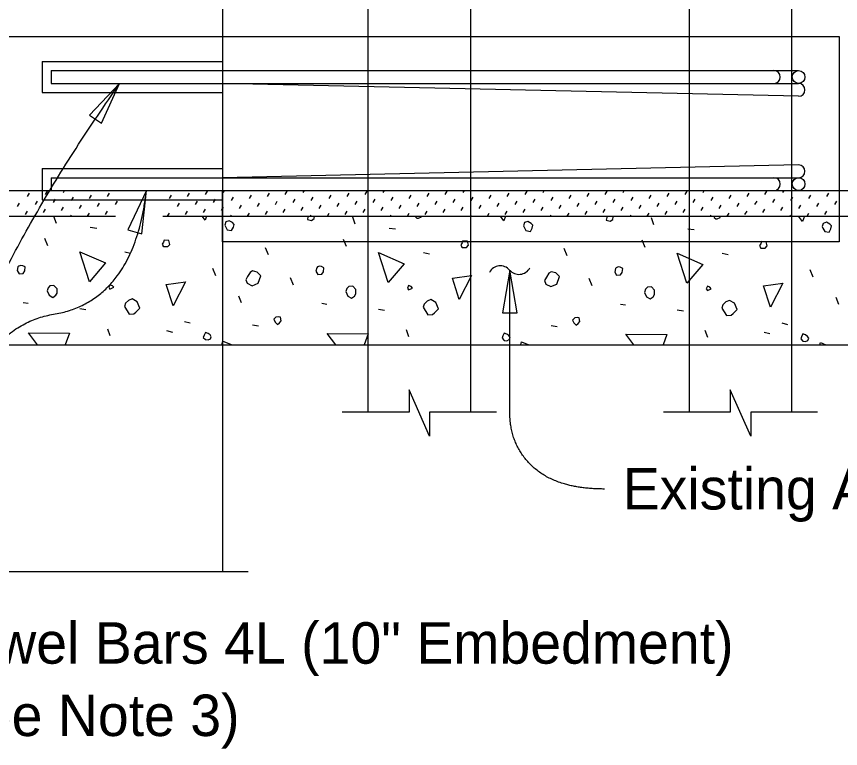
# Model space of a CAD drawing. Extents: x 1 to 39.2, y 0 to 26.
# Drawn here: x 29.063 to 33.072, y 8.169 to 11.73 of the extents above; entities that cross this region are included whole.
import ezdxf

# ---------------------------------------------------------------- set-up
doc = ezdxf.new("R2010")
doc.units = 0
for name, color, linetype in [('Dimension', 7, 'Continuous'), ('Miscellaneous', 7, 'Continuous'), ('Rebar', 7, 'Continuous'), ('TextStructures', 7, 'Continuous'), ('TrafBarrierConc', 7, 'Continuous')]:
    doc.layers.add(name, color=color, linetype=linetype)

msp = doc.modelspace()

# ---------------------------------------------------------------- linework, layer by layer
at = {"layer": 'Dimension'}
for points in [[(29.5637, 11.4029), (29.4175, 11.2504), (29.4758, 11.2108)], [(29.695, 10.8824), (29.6045, 10.6915), (29.6724, 10.6724)], [(31.4629, 10.4959), (31.4278, 10.2877), (31.4984, 10.2877)]]:
    msp.add_lwpolyline(points, close=True, dxfattribs=at)
for points in [[(31.3975, 9.8041), (31.0722, 9.8041), (31.0722, 9.6878), (30.9728, 9.9128), (30.9728, 9.8041), (30.6475, 9.8041)], [(32.96, 9.8041), (32.6347, 9.8041), (32.6347, 9.6878), (32.5353, 9.9128), (32.5353, 9.8041), (32.21, 9.8041)], [(30.1906, 9.0282), (28.3006, 9.0282), (28.3006, 8.912), (28.2013, 9.137), (28.2013, 9.0282), (26.9206, 9.0282)]]:
    msp.add_lwpolyline(points, dxfattribs=at)
for centre, start, end in [((31.4168, 10.4571), 40.6168, 152.344), ((31.5073, 10.5347), 220.6168, 332.344)]:
    msp.add_arc(centre, 0.0596, start, end, dxfattribs=at)
for points in [[(28.5243, 8.6625), (28.4652, 8.6625), (28.4062, 8.6794), (28.4062, 8.9032), (28.932, 10.5005), (29.5637, 11.4029)], [(28.5774, 9.3946), (28.84, 10.2158), (29.6329, 10.3433), (29.6949, 10.8824)], [(31.9229, 9.431), (31.6965, 9.431), (31.4629, 9.6392), (31.4629, 9.9681), (31.4629, 10.4959)]]:
    msp.add_open_spline(points, degree=2, dxfattribs=at)
at = {"layer": 'Miscellaneous'}
for p, q in [((29.1166, 10.8538), (29.1263, 10.8706)), ((29.2041, 10.8635), (29.2138, 10.8803)), ((29.2916, 10.8732), (29.2972, 10.883)), ((29.5055, 10.8538), (29.5152, 10.8706)), ((29.8944, 10.8538), (29.9041, 10.8706)), ((29.9819, 10.8635), (29.9916, 10.8803)), ((30.0694, 10.8732), (30.075, 10.883)), ((30.2833, 10.8538), (30.293, 10.8706)), ((30.3708, 10.8635), (30.3805, 10.8803)), ((30.4583, 10.8732), (30.4639, 10.883)), ((30.6722, 10.8538), (30.6819, 10.8706)), ((30.7597, 10.8635), (30.7694, 10.8803)), ((30.8472, 10.8732), (30.8528, 10.883)), ((31.0611, 10.8538), (31.0708, 10.8706)), ((31.1486, 10.8635), (31.1583, 10.8803)), ((31.2361, 10.8732), (31.2418, 10.883)), ((31.45, 10.8538), (31.4597, 10.8706)), ((31.5375, 10.8635), (31.5473, 10.8803)), ((31.625, 10.8732), (31.6307, 10.883)), ((31.8389, 10.8538), (31.8487, 10.8706)), ((31.9264, 10.8635), (31.9362, 10.8803)), ((32.0139, 10.8732), (32.0196, 10.883)), ((32.2278, 10.8538), (32.2376, 10.8706)), ((32.3153, 10.8635), (32.3251, 10.8803)), ((32.4029, 10.8732), (32.4085, 10.883)), ((32.6168, 10.8538), (32.6265, 10.8706)), ((32.7043, 10.8635), (32.714, 10.8803)), ((32.7918, 10.8732), (32.7974, 10.883)), ((33.0057, 10.8538), (33.0154, 10.8706)), ((29.1555, 10.8149), (29.1652, 10.8317)), ((29.243, 10.8246), (29.2527, 10.8414)), ((29.3305, 10.8344), (29.3402, 10.8511)), ((29.418, 10.8441), (29.4277, 10.8609)), ((29.5444, 10.8149), (29.5541, 10.8317)), ((29.8069, 10.8441), (29.8166, 10.8609)), ((29.9333, 10.8149), (29.943, 10.8317)), ((30.0208, 10.8246), (30.0305, 10.8414)), ((30.1083, 10.8344), (30.118, 10.8511)), ((30.1958, 10.8441), (30.2055, 10.8609)), ((30.3222, 10.8149), (30.3319, 10.8317)), ((30.4097, 10.8246), (30.4194, 10.8414)), ((30.4972, 10.8344), (30.5069, 10.8511)), ((30.5847, 10.8441), (30.5944, 10.8609)), ((30.7111, 10.8149), (30.7208, 10.8317)), ((30.7986, 10.8246), (30.8083, 10.8414)), ((30.8861, 10.8344), (30.8958, 10.8511)), ((30.9736, 10.8441), (30.9833, 10.8609)), ((31.1, 10.8149), (31.1097, 10.8317)), ((31.1875, 10.8246), (31.1972, 10.8414)), ((31.275, 10.8344), (31.2847, 10.8511)), ((31.3625, 10.8441), (31.3722, 10.8609)), ((31.4889, 10.8149), (31.4986, 10.8317)), ((31.5764, 10.8246), (31.5861, 10.8414)), ((31.6639, 10.8344), (31.6736, 10.8511)), ((31.7514, 10.8441), (31.7612, 10.8609)), ((31.8778, 10.8149), (31.8875, 10.8317)), ((31.9653, 10.8246), (31.9751, 10.8414)), ((32.0528, 10.8344), (32.0626, 10.8511)), ((32.1403, 10.8441), (32.1501, 10.8609)), ((32.2667, 10.8149), (32.2765, 10.8317)), ((32.3542, 10.8246), (32.364, 10.8414)), ((32.4417, 10.8344), (32.4515, 10.8511)), ((32.5292, 10.8441), (32.539, 10.8609)), ((32.6556, 10.8149), (32.6654, 10.8317)), ((32.7431, 10.8246), (32.7529, 10.8414)), ((32.8307, 10.8344), (32.8404, 10.8511)), ((32.9182, 10.8441), (32.9279, 10.8609)), ((33.0446, 10.8149), (33.0543, 10.8317)), ((29.068, 10.8052), (29.0777, 10.822)), ((29.1944, 10.776), (29.2041, 10.7928)), ((29.2819, 10.7857), (29.2916, 10.8025)), ((29.3694, 10.7955), (29.3791, 10.8123)), ((29.4569, 10.8052), (29.4666, 10.822)), ((29.8458, 10.8052), (29.8555, 10.822)), ((29.9722, 10.776), (29.9819, 10.7928)), ((30.0597, 10.7857), (30.0694, 10.8025)), ((30.1472, 10.7955), (30.1569, 10.8123)), ((30.2347, 10.8052), (30.2444, 10.822)), ((30.3611, 10.776), (30.3708, 10.7928)), ((30.4486, 10.7857), (30.4583, 10.8025)), ((30.5361, 10.7955), (30.5458, 10.8123)), ((30.6236, 10.8052), (30.6333, 10.822)), ((30.75, 10.776), (30.7597, 10.7928)), ((30.8375, 10.7857), (30.8472, 10.8025)), ((30.925, 10.7955), (30.9347, 10.8123)), ((31.0125, 10.8052), (31.0222, 10.822)), ((31.1389, 10.776), (31.1486, 10.7928)), ((31.2264, 10.7857), (31.2361, 10.8025)), ((31.3139, 10.7955), (31.3236, 10.8123)), ((31.4014, 10.8052), (31.4111, 10.822)), ((31.5278, 10.776), (31.5375, 10.7928)), ((31.6153, 10.7857), (31.625, 10.8025)), ((31.7028, 10.7955), (31.7125, 10.8123)), ((31.7903, 10.8052), (31.8, 10.822)), ((31.9167, 10.776), (31.9264, 10.7928)), ((32.0042, 10.7857), (32.0139, 10.8025)), ((32.0917, 10.7955), (32.1014, 10.8123)), ((32.1792, 10.8052), (32.189, 10.822)), ((32.3056, 10.776), (32.3153, 10.7928)), ((32.3931, 10.7857), (32.4029, 10.8025)), ((32.4806, 10.7955), (32.4904, 10.8123)), ((32.5681, 10.8052), (32.5779, 10.822)), ((32.6945, 10.776), (32.7043, 10.7928)), ((32.782, 10.7857), (32.7918, 10.8025)), ((32.8695, 10.7955), (32.8793, 10.8123)), ((32.957, 10.8052), (32.9668, 10.822)), ((29.1069, 10.7663), (29.1166, 10.7831)), ((29.2577, 10.7234), (29.2453, 10.757)), ((29.3272, 10.758), (29.3305, 10.7636)), ((29.4091, 10.758), (29.418, 10.7734)), ((29.4958, 10.7663), (29.5055, 10.7831)), ((29.798, 10.758), (29.8069, 10.7734)), ((29.8847, 10.7663), (29.8944, 10.7831)), ((30.105, 10.758), (30.1083, 10.7636)), ((30.1869, 10.758), (30.1958, 10.7734)), ((30.2736, 10.7663), (30.2833, 10.7831)), ((30.4939, 10.758), (30.4972, 10.7636)), ((30.5758, 10.758), (30.5847, 10.7734)), ((30.6625, 10.7663), (30.6722, 10.7831)), ((30.7108, 10.7199), (30.6984, 10.7535)), ((30.8828, 10.758), (30.8861, 10.7636)), ((30.9647, 10.758), (30.9736, 10.7734)), ((31.0514, 10.7663), (31.0611, 10.7831)), ((31.2717, 10.758), (31.275, 10.7636)), ((31.3536, 10.758), (31.3625, 10.7734)), ((31.4403, 10.7663), (31.45, 10.7831)), ((31.6606, 10.758), (31.6639, 10.7636)), ((31.7425, 10.758), (31.7514, 10.7734)), ((31.8292, 10.7663), (31.8389, 10.7831)), ((32.0496, 10.758), (32.0528, 10.7636)), ((32.1314, 10.758), (32.1403, 10.7734)), ((32.1639, 10.7163), (32.1515, 10.7499)), ((32.2181, 10.7663), (32.2278, 10.7831)), ((32.4385, 10.758), (32.4417, 10.7636)), ((32.5203, 10.758), (32.5292, 10.7734)), ((32.607, 10.7663), (32.6168, 10.7831)), ((32.8274, 10.758), (32.8307, 10.7636)), ((32.9092, 10.758), (32.9182, 10.7734)), ((32.9959, 10.7663), (33.0057, 10.7831)), ((29.4221, 10.704), (29.4539, 10.7004)), ((30.8752, 10.7004), (30.907, 10.6969)), ((32.3283, 10.6969), (32.3601, 10.6934)), ((29.2153, 10.6138), (29.2011, 10.6492)), ((30.6684, 10.6103), (30.6542, 10.6456)), ((32.1215, 10.6067), (32.1073, 10.6421)), ((29.59, 10.5855), (29.6183, 10.5784)), ((30.2883, 10.5696), (30.2741, 10.605)), ((31.7414, 10.5661), (31.7273, 10.6014)), ((31.0431, 10.582), (31.0714, 10.5749)), ((32.4962, 10.5784), (32.5245, 10.5714)), ((30.032, 10.4688), (30.0178, 10.5042)), ((32.9382, 10.4618), (32.924, 10.4971)), ((30.4103, 10.4229), (30.3961, 10.4582)), ((31.8634, 10.4193), (31.8492, 10.4547)), ((30.1575, 10.3363), (30.1451, 10.3699)), ((33.0637, 10.3292), (33.0513, 10.3628)), ((29.095, 10.338), (29.1198, 10.3345)), ((29.3708, 10.3097), (29.4009, 10.3044)), ((30.5481, 10.3345), (30.5729, 10.331)), ((30.8239, 10.3062), (30.854, 10.3009)), ((32.0013, 10.331), (32.026, 10.3274)), ((32.277, 10.3027), (32.3071, 10.2974)), ((29.8799, 10.2461), (29.9082, 10.239)), ((30.2105, 10.2302), (30.2406, 10.2249)), ((31.6636, 10.2267), (31.6937, 10.2214)), ((32.7861, 10.239), (32.8144, 10.232)), ((29.5193, 10.1754), (29.5069, 10.209)), ((29.7933, 10.2019), (29.8216, 10.1948)), ((30.9724, 10.1719), (30.96, 10.2054)), ((32.4255, 10.1683), (32.4131, 10.2019)), ((32.6995, 10.1948), (32.7278, 10.1878))]:
    msp.add_line(p, q, dxfattribs=at)
for points in [[(31.2725, 9.8041), (31.2725, 13.5329), (30.7725, 13.5329), (30.7725, 9.8041)], [(32.835, 9.8041), (32.835, 13.5329), (32.335, 13.5329), (32.335, 9.8041)], [(29.9807, 10.7393), (29.9665, 10.758)], [(29.9877, 10.758), (29.9807, 10.7393)], [(30.4792, 10.7429), (30.4987, 10.7375), (30.511, 10.7464), (30.5127, 10.758)], [(30.4814, 10.758), (30.481, 10.7552), (30.4792, 10.7429)], [(31.0033, 10.758), (31.0042, 10.7552), (31.0113, 10.7482)], [(31.0113, 10.7482), (31.0184, 10.7482), (31.0325, 10.7552), (31.0334, 10.758)], [(31.4338, 10.7358), (31.4169, 10.758)], [(31.4421, 10.758), (31.4338, 10.7358)], [(31.9323, 10.7393), (31.9518, 10.734), (31.9641, 10.7429), (31.9659, 10.7552), (31.9632, 10.758)], [(31.935, 10.758), (31.9341, 10.7517), (31.9323, 10.7393)], [(32.4552, 10.758), (32.4573, 10.7517), (32.4644, 10.7446)], [(32.4644, 10.7446), (32.4715, 10.7446), (32.4856, 10.7517), (32.4877, 10.758)], [(32.8869, 10.7322), (32.8674, 10.758)], [(32.8965, 10.758), (32.8869, 10.7322)], [(30.0797, 10.7075), (30.0885, 10.6916), (30.1097, 10.6881), (30.1186, 10.704), (30.1221, 10.7181), (30.1133, 10.7269), (30.0974, 10.7358), (30.0815, 10.7305), (30.0762, 10.7146), (30.0797, 10.7075)], [(31.5328, 10.704), (31.5416, 10.6881), (31.5628, 10.6845), (31.5717, 10.7004), (31.5752, 10.7146), (31.5664, 10.7234), (31.5505, 10.7322), (31.5346, 10.7269), (31.5293, 10.711), (31.5328, 10.704)], [(32.9859, 10.7004), (32.9947, 10.6845), (33.016, 10.681), (33.0248, 10.6969), (33.0283, 10.711), (33.0195, 10.7199), (33.0036, 10.7287), (32.9877, 10.7234), (32.9824, 10.7075), (32.9859, 10.7004)], [(29.7774, 10.6103), (29.7986, 10.6103), (29.8092, 10.6209), (29.8039, 10.6403), (29.7809, 10.6421), (29.7774, 10.6315), (29.7721, 10.6226), (29.7774, 10.6103), (29.7739, 10.6138)], [(31.2305, 10.6067), (31.2517, 10.6067), (31.2623, 10.6173), (31.257, 10.6368), (31.234, 10.6386), (31.2305, 10.6279), (31.2252, 10.6191), (31.2305, 10.6067), (31.227, 10.6103)], [(32.6836, 10.6032), (32.7048, 10.6032), (32.7154, 10.6138), (32.7101, 10.6332), (32.6871, 10.635), (32.6836, 10.6244), (32.6783, 10.6156), (32.6836, 10.6032), (32.6801, 10.6067)], [(29.4185, 10.4388), (29.3708, 10.5855), (29.4963, 10.5307), (29.4185, 10.4388)], [(30.8717, 10.4353), (30.8239, 10.582), (30.9494, 10.5272), (30.8717, 10.4353)], [(32.3248, 10.4317), (32.277, 10.5784), (32.4025, 10.5236), (32.3248, 10.4317)], [(29.0668, 10.4936), (29.0756, 10.4777), (29.095, 10.4795), (29.1039, 10.4918), (29.1057, 10.5113), (29.0933, 10.5166), (29.0844, 10.5183), (29.0738, 10.5148), (29.0703, 10.5113), (29.0668, 10.4936)], [(30.5199, 10.4901), (30.5287, 10.4742), (30.5481, 10.4759), (30.557, 10.4883), (30.5588, 10.5077), (30.5464, 10.513), (30.5375, 10.5148), (30.5269, 10.5113), (30.5234, 10.5077), (30.5199, 10.4901)], [(31.973, 10.4865), (31.9818, 10.4706), (32.0013, 10.4724), (32.0101, 10.4848), (32.0119, 10.5042), (31.9995, 10.5095), (31.9906, 10.5113), (31.98, 10.5077), (31.9765, 10.5042), (31.973, 10.4865)], [(30.1858, 10.4317), (30.2087, 10.4193), (30.2388, 10.4317), (30.2512, 10.4688), (30.2335, 10.4865), (30.2105, 10.4918), (30.1999, 10.4848), (30.1875, 10.4653), (30.1787, 10.4494), (30.1858, 10.4317)], [(31.2169, 10.353), (31.1833, 10.4573), (31.277, 10.4697), (31.2169, 10.353)], [(31.6389, 10.4282), (31.6618, 10.4158), (31.6919, 10.4282), (31.7043, 10.4653), (31.6866, 10.483), (31.6636, 10.4883), (31.653, 10.4812), (31.6406, 10.4618), (31.6318, 10.4459), (31.6389, 10.4282)], [(29.5175, 10.4034), (29.537, 10.4123), (29.5299, 10.4193), (29.5175, 10.4247), (29.5122, 10.4123), (29.5175, 10.4034)], [(29.8251, 10.3221), (29.7915, 10.4264), (29.8852, 10.4388), (29.8251, 10.3221)], [(32.7313, 10.3151), (32.6978, 10.4193), (32.7914, 10.4317), (32.7313, 10.3151)], [(29.2117, 10.3946), (29.2223, 10.3734), (29.24, 10.3628), (29.2541, 10.3734), (29.2612, 10.384), (29.2612, 10.4052), (29.2453, 10.4211), (29.2259, 10.4193), (29.217, 10.4105), (29.2117, 10.3946)], [(30.6648, 10.3911), (30.6754, 10.3699), (30.6931, 10.3592), (30.7072, 10.3699), (30.7143, 10.3805), (30.7143, 10.4017), (30.6984, 10.4176), (30.679, 10.4158), (30.6701, 10.407), (30.6648, 10.3911)], [(30.9706, 10.3999), (30.9901, 10.4087), (30.983, 10.4158), (30.9706, 10.4211), (30.9653, 10.4087), (30.9706, 10.3999)], [(32.1179, 10.3875), (32.1285, 10.3663), (32.1462, 10.3557), (32.1604, 10.3663), (32.1674, 10.3769), (32.1674, 10.3981), (32.1515, 10.414), (32.1321, 10.4123), (32.1232, 10.4034), (32.1179, 10.3875)], [(32.4238, 10.3964), (32.4432, 10.4052), (32.4361, 10.4123), (32.4238, 10.4176), (32.4184, 10.4052), (32.4238, 10.3964)], [(29.5883, 10.3186), (29.6112, 10.2815), (29.6342, 10.2832), (29.6431, 10.2921), (29.6625, 10.3115), (29.6501, 10.3416), (29.6254, 10.3557), (29.6077, 10.3486), (29.5936, 10.3345), (29.5883, 10.3186)], [(31.0414, 10.3151), (31.0643, 10.2779), (31.0873, 10.2797), (31.0962, 10.2885), (31.1156, 10.308), (31.1032, 10.338), (31.0785, 10.3522), (31.0608, 10.3451), (31.0467, 10.331), (31.0414, 10.3151)], [(32.4945, 10.3115), (32.5174, 10.2744), (32.5404, 10.2762), (32.5493, 10.285), (32.5687, 10.3044), (32.5563, 10.3345), (32.5316, 10.3486), (32.5139, 10.3416), (32.4998, 10.3274), (32.4945, 10.3115)], [(30.3219, 10.2426), (30.3325, 10.232), (30.3431, 10.239), (30.3502, 10.2496), (30.3466, 10.2673), (30.3378, 10.2691), (30.3254, 10.2673), (30.3148, 10.2567), (30.3219, 10.2426)], [(31.775, 10.239), (31.7856, 10.2284), (31.7962, 10.2355), (31.8033, 10.2461), (31.7997, 10.2638), (31.7909, 10.2656), (31.7785, 10.2638), (31.7679, 10.2532), (31.775, 10.239)], [(29.1659, 10.133), (29.1216, 10.1913), (29.3213, 10.1895), (29.3002, 10.133)], [(29.9825, 10.1577), (29.9948, 10.156), (30.0072, 10.1613), (30.0107, 10.1719), (30.0054, 10.1807), (29.9948, 10.1878), (29.9825, 10.1931), (29.9754, 10.1789), (29.9719, 10.1683), (29.9825, 10.1577)], [(30.6163, 10.133), (30.5747, 10.1878), (30.7744, 10.186), (30.7546, 10.133)], [(31.4356, 10.1542), (31.4479, 10.1524), (31.4603, 10.1577), (31.4639, 10.1683), (31.4585, 10.1772), (31.4479, 10.1842), (31.4356, 10.1895), (31.4285, 10.1754), (31.425, 10.1648), (31.4356, 10.1542)], [(32.0667, 10.133), (32.0278, 10.1842), (32.2275, 10.1825), (32.209, 10.133)], [(32.8887, 10.1506), (32.901, 10.1489), (32.9134, 10.1542), (32.917, 10.1648), (32.9117, 10.1736), (32.901, 10.1807), (32.8887, 10.186), (32.8816, 10.1719), (32.8781, 10.1613), (32.8887, 10.1506)], [(30.0619, 10.133), (30.0673, 10.1506), (30.1119, 10.133)], [(31.5161, 10.133), (31.5204, 10.1471), (31.5561, 10.133)], [(32.9703, 10.133), (32.9735, 10.1436), (33.0003, 10.133)]]:
    msp.add_lwpolyline(points, dxfattribs=at)
at = {"layer": 'Rebar'}
for p, q in [((29.2322, 11.4663), (32.8677, 11.4663)), ((29.2322, 11.4663), (29.2322, 11.4038)), ((29.2322, 11.4038), (32.8677, 11.4038)), ((32.8677, 11.3414), (30.0656, 11.4038)), ((32.8677, 11.0079), (30.0656, 10.9455)), ((29.2322, 10.9455), (32.8677, 10.9455)), ((29.2322, 10.9455), (29.2322, 10.883)), ((29.2322, 10.883), (32.8677, 10.883))]:
    msp.add_line(p, q, dxfattribs=at)
for centre in [(32.8677, 11.435), (32.8677, 10.9142)]:
    msp.add_circle(centre, 0.0312, dxfattribs=at)
for centre in [(32.7474, 11.4351), (32.8677, 11.3726), (32.8677, 11.3726), (32.8677, 10.9767), (32.7474, 10.9143)]:
    msp.add_arc(centre, 0.0312, 270, 90, dxfattribs=at)
at = {"layer": 'TrafBarrierConc'}
for p, q in [((30.0656, 13.5496), (30.0656, 10.883)), ((27.0456, 11.633), (33.0656, 11.633)), ((33.0656, 11.633), (33.0656, 10.883)), ((29.1878, 11.5107), (30.0656, 11.5107)), ((29.1878, 11.5107), (29.1878, 11.3594)), ((29.1878, 11.3594), (30.0656, 11.3594)), ((29.1878, 10.9899), (30.0656, 10.9899)), ((29.1878, 10.9899), (29.1878, 10.8385)), ((27.0456, 10.883), (29.6048, 10.883)), ((29.7751, 10.883), (34.904, 10.883)), ((30.0656, 10.8829), (30.0656, 9.0282)), ((29.1878, 10.8385), (30.0656, 10.8385)), ((27.0656, 10.758), (29.5452, 10.758)), ((29.7751, 10.758), (34.9091, 10.758)), ((27.0656, 10.133), (34.904, 10.133))]:
    msp.add_line(p, q, dxfattribs=at)
msp.add_lwpolyline([(33.0656, 11.633), (33.0656, 10.633), (30.0656, 10.633), (30.0656, 10.883)], dxfattribs=at)

# ---------------------------------------------------------------- texts
at = {"layer": 'Dimension'}
for s, p in [('Dowel Bars 4L (10" Embedment) ', (28.6198, 8.5814)), ('(See Note 3)', (28.6198, 8.2294))]:
    msp.add_text(s, height=0.2016, dxfattribs=at).set_placement(p)
at = {"layer": 'TextStructures'}
msp.add_text('Existing Approach Slab', height=0.2016, dxfattribs=at).set_placement((32.0121, 9.3315))

doc.saveas('drawing.dxf')
